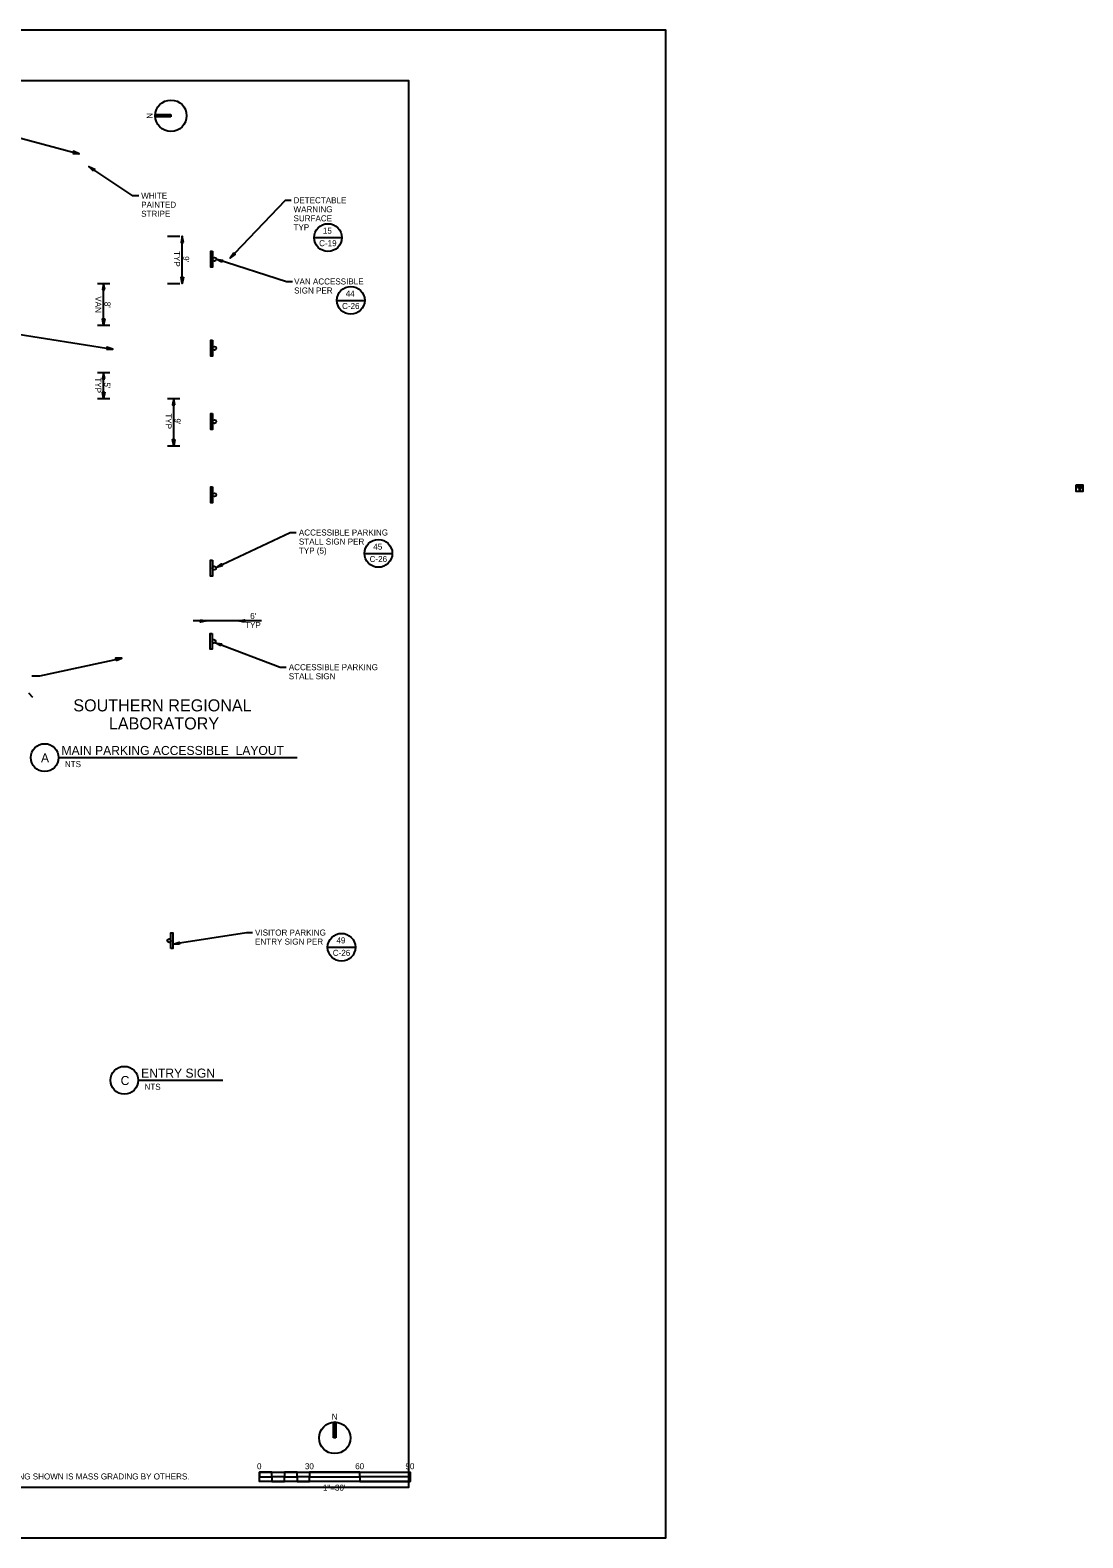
# Model space of a CAD drawing. Extents: x 0 to 4.19, y 0 to 2.5.
# Drawn here: x 2.446 to 4.191, y 0 to 2.5 of the extents above; entities that cross this region are included whole.
import ezdxf

# ---------------------------------------------------------------- set-up
doc = ezdxf.new("R2010")
doc.units = 0
for name, color, linetype in [('C-MARK', 7, 'Continuous'), ('C-PRKG-CONC', 7, 'Continuous'), ('C-TEXT', 7, 'Continuous'), ('C-TEXT-SUBT', 7, 'Continuous'), ('C-TEXT-TITL', 7, 'Continuous'), ('Default', 7, 'Continuous'), ('G-SYMB', 7, 'Continuous'), ('G-TEXT', 7, 'Continuous'), ('G-TTLB-OTLN', 7, 'Continuous'), ('G-TTLB-VIEW', 7, 'Continuous'), ('Level 11', 7, 'Continuous')]:
    doc.layers.add(name, color=color, linetype=linetype)

# ---------------------------------------------------------------- blocks, each defined once
blk = doc.blocks.new('G-handy2')
at = {"layer": 'Default'}
for p, q in [((-0.0006, 0.0019), (-0.0004, 0.0015)), ((0, 0), (-0.0002, 0.0036)), ((0, 0), (0.0033, 0)), ((0.0004, 0.0014), (0.0003, 0.0028)), ((0.0021, 0.0014), (0.0004, 0.0014)), ((0.0004, 0.0009), (0.0021, 0.0009)), ((0.0004, 0.0005), (0.0004, 0.0009)), ((0.0004, 0.0005), (0.0037, 0.0005)), ((0.0021, 0.0009), (0.0021, 0.0014)), ((0.0033, 0), (0.0039, -0.0023)), ((0.0037, 0.0005), (0.0042, -0.0017)), ((0.0027, -0.0011), (0.0031, -0.0012)), ((0.0039, -0.0023), (0.0049, -0.002)), ((0.0042, -0.0017), (0.0048, -0.0015)), ((0.0048, -0.0015), (0.0049, -0.002))]:
    blk.add_line(p, q, dxfattribs=at)
for centre, radius, start, end in [((0.0007, -0.0004), 0.00261, 117.724, 341.902), ((0.0007, -0.0004), 0.00219, 117.724, 341.902), ((0.0005, 0.0035), 0.000712, 254.4441, 174.7331)]:
    blk.add_arc(centre, radius, start, end, dxfattribs=at)

msp = doc.modelspace()

# ---------------------------------------------------------------- linework, layer by layer
at = {"layer": 'C-MARK'}
for p, q in [((2.6734, 2.1583), (2.6937, 2.1583)), ((2.6978, 2.0801), (2.6978, 2.1583)), ((2.9164, 2.1561), (2.9624, 2.1561)), ((2.5571, 2.0801), (2.5774, 2.0801)), ((2.5673, 2.0107), (2.5673, 2.0801)), ((2.6733, 2.0801), (2.6935, 2.0801)), ((2.9543, 2.0519), (3.0003, 2.0519)), ((2.5571, 2.0107), (2.5774, 2.0107)), ((2.5571, 1.9326), (2.5774, 1.9326)), ((2.5673, 1.8892), (2.5673, 1.9326)), ((2.5571, 1.8892), (2.5774, 1.8892)), ((2.6734, 1.8892), (2.6937, 1.8892)), ((2.6836, 1.811), (2.6836, 1.8892)), ((2.6733, 1.811), (2.6935, 1.811)), ((3.0001, 1.6323), (3.0461, 1.6323)), ((2.8291, 1.5204), (2.7156, 1.5204)), ((2.9389, 0.9793), (2.9849, 0.9793))]:
    msp.add_line(p, q, dxfattribs=at)
for points in [[(2.3741, 2.3331), (2.3841, 2.3331), (2.527, 2.2947)], [(2.626, 2.2252), (2.616, 2.2252), (2.5429, 2.2737)], [(2.8804, 2.0828), (2.8704, 2.0828), (2.7542, 2.1201)], [(2.4051, 1.9978), (2.4151, 1.9978), (2.5829, 1.9711)], [(2.8869, 1.6665), (2.8769, 1.6665), (2.7543, 1.6092)], [(2.8701, 1.4432), (2.8601, 1.4432), (2.7525, 1.4843)], [(2.4483, 1.4292), (2.4617, 1.4292), (2.5978, 1.4589)], [(2.8142, 1.0032), (2.8042, 1.0032), (2.6829, 0.9845)]]:
    msp.add_lwpolyline(points, dxfattribs=at)
for points in [[(2.7482, 2.1333), (2.7482, 2.1069), (2.745, 2.1069), (2.745, 2.1333)], [(2.7482, 1.9858), (2.7482, 1.9594), (2.745, 1.9594), (2.745, 1.9858)], [(2.7482, 1.8642), (2.7482, 1.8378), (2.745, 1.8378), (2.745, 1.8642)], [(2.7482, 1.7427), (2.7482, 1.7163), (2.745, 1.7163), (2.745, 1.7427)], [(2.7478, 1.6212), (2.7478, 1.5948), (2.7446, 1.5948), (2.7446, 1.6212)], [(2.7474, 1.4997), (2.7474, 1.4733), (2.7442, 1.4733), (2.7442, 1.4997)], [(2.6789, 0.977), (2.6789, 1.0034), (2.6821, 1.0034), (2.6821, 0.977)]]:
    msp.add_lwpolyline(points, close=True, dxfattribs=at)
for centre, radius in [((2.9394, 2.1561), 0.023), ((2.7512, 2.1201), 0.003), ((2.9773, 2.0519), 0.023), ((2.7512, 1.9726), 0.003), ((2.7512, 1.851), 0.003), ((2.7512, 1.7295), 0.003), ((3.0231, 1.6323), 0.023), ((2.7508, 1.608), 0.003), ((2.7504, 1.4865), 0.003), ((2.9619, 0.9793), 0.023), ((2.6759, 0.9902), 0.003)]:
    msp.add_circle(centre, radius, dxfattribs=at)
at = {"layer": 'C-PRKG-CONC'}
msp.add_lwpolyline([(4.1803, 1.7463), (4.1914, 1.7463), (4.1914, 1.7352), (4.1803, 1.7352)], close=True, dxfattribs=at)
msp.add_lwpolyline([(4.1803, 1.7463), (4.1914, 1.7463), (4.1914, 1.7352), (4.1803, 1.7352)], close=True, dxfattribs=at)
at = {"layer": 'C-TEXT'}
for p, q in [((2.4926, 1.2938), (2.8882, 1.2938)), ((2.6247, 0.7588), (2.7651, 0.7588))]:
    msp.add_line(p, q, dxfattribs=at)
for points in [[(2.5165, 2.2956), (2.527, 2.2947), (2.5174, 2.2992)], [(2.5505, 2.2664), (2.5429, 2.2737), (2.5526, 2.2695)], [(2.6996, 2.1478), (2.6978, 2.1583), (2.6959, 2.1478)], [(2.7832, 2.1307), (2.7773, 2.1219), (2.7858, 2.1282)], [(2.7636, 2.1152), (2.7542, 2.1201), (2.7647, 2.1187)], [(2.5691, 2.0697), (2.5673, 2.0801), (2.5655, 2.0697)], [(2.6996, 2.0905), (2.6978, 2.0801), (2.6959, 2.0905)], [(2.5691, 2.0211), (2.5673, 2.0107), (2.5655, 2.0211)], [(2.5723, 1.9709), (2.5829, 1.9711), (2.5729, 1.9745)], [(2.5691, 1.9221), (2.5673, 1.9326), (2.5655, 1.9221)], [(2.5691, 1.8996), (2.5673, 1.8892), (2.5655, 1.8996)], [(2.6854, 1.8787), (2.6836, 1.8892), (2.6817, 1.8787)], [(2.6854, 1.8215), (2.6836, 1.811), (2.6817, 1.8215)], [(2.7645, 1.6119), (2.7543, 1.6092), (2.7629, 1.6152)], [(2.7281, 1.5222), (2.7385, 1.5204), (2.7281, 1.5185)], [(2.8008, 1.5185), (2.7904, 1.5204), (2.8008, 1.5222)], [(2.7616, 1.4789), (2.7525, 1.4843), (2.7629, 1.4823)], [(2.588, 1.4549), (2.5978, 1.4589), (2.5873, 1.4584)], [(2.6934, 0.9843), (2.6829, 0.9845), (2.6929, 0.9879)]]:
    msp.add_lwpolyline(points, close=True, dxfattribs=at)
msp.add_lwpolyline([(2.8786, 2.2175), (2.8686, 2.2175), (2.7845, 2.1294)], dxfattribs=at)
for centre in [(2.4696, 1.2938), (2.6017, 0.7588)]:
    msp.add_circle(centre, 0.023, dxfattribs=at)
at = {"layer": 'G-SYMB'}
for p, q in [((2.679, 2.3586), (2.6532, 2.3586)), ((2.679, 2.3577), (2.6532, 2.3577)), ((2.6533, 2.36), (2.679, 2.36)), ((2.679, 2.3563), (2.6533, 2.3563)), ((2.679, 2.36), (2.679, 2.3563)), ((2.9488, 0.1657), (2.9488, 0.1915)), ((2.9503, 0.1657), (2.9503, 0.1915)), ((2.9511, 0.1657), (2.9511, 0.1915)), ((2.9525, 0.1915), (2.9525, 0.1657)), ((2.9525, 0.1657), (2.9488, 0.1657))]:
    msp.add_line(p, q, dxfattribs=at)
for points in [[(2.8257, 0.101), (2.8465, 0.101), (2.8465, 0.1088), (2.8257, 0.1088)], [(2.8257, 0.1088), (3.0757, 0.1088), (3.0757, 0.0932), (2.8257, 0.0932)], [(2.8465, 0.0932), (2.8673, 0.0932), (2.8673, 0.101), (2.8465, 0.101)], [(2.8673, 0.101), (2.8882, 0.101), (2.8882, 0.1088), (2.8673, 0.1088)], [(2.8882, 0.0932), (2.909, 0.0932), (2.909, 0.101), (2.8882, 0.101)], [(2.909, 0.101), (2.9923, 0.101), (2.9923, 0.1088), (2.909, 0.1088)], [(2.9923, 0.0932), (3.0757, 0.0932), (3.0757, 0.101), (2.9923, 0.101)]]:
    msp.add_lwpolyline(points, close=True, dxfattribs=at)
for centre in [(2.679, 2.3581), (2.9507, 0.1657)]:
    msp.add_circle(centre, 0.026, dxfattribs=at)
for centre, start, end in [((2.678, 2.3581), 175.7578, 184.2422), ((2.9507, 0.1668), 85.7578, 94.2422)]:
    msp.add_arc(centre, 0.0248, start, end, dxfattribs=at)
at = {"layer": 'G-TTLB-OTLN'}
msp.add_lwpolyline([(0, 0), (3.5, 0), (3.5, 2.5), (0, 2.5)], close=True, dxfattribs=at)
msp.add_lwpolyline([(0, 0), (3.5, 0), (3.5, 2.5), (0, 2.5)], close=True, dxfattribs=at)
at = {"layer": 'G-TTLB-VIEW'}
msp.add_lwpolyline([(0.1667, 2.4167), (3.0729, 2.4167), (3.0729, 0.0833), (0.1667, 0.0833)], close=True, dxfattribs=at)
at = {"layer": 'Level 11'}
msp.add_line((2.4502, 1.3937), (2.4433, 1.4005), dxfattribs=at)

# ---------------------------------------------------------------- block references
at = {"layer": 'C-PRKG-CONC', "xscale": 1.1453414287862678, "yscale": 1.1453414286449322, "rotation": 179.73949444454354}
msp.add_blockref('G-handy2', (4.1867, 1.7415), dxfattribs=at)

# ---------------------------------------------------------------- texts
at = {"layer": 'C-TEXT'}
for s, p in [('WHITE', (2.6297, 2.2205)), ('STRIPE', (2.6297, 2.1905)), ('PAINTED', (2.6297, 2.2055)), ('WARNING', (2.8823, 2.198)), ('DETECTABLE', (2.8823, 2.213)), ('TYP', (2.8823, 2.168)), ('SURFACE', (2.8823, 2.183)), ('C-19', (2.9248, 2.1418)), ('15', (2.931, 2.1625)), ('VAN ACCESSIBLE', (2.8833, 2.0783)), ('SIGN PER', (2.8833, 2.0633)), ('44', (2.9689, 2.0582)), ('C-26', (2.9628, 2.0376)), ('ACCESSIBLE PARKING', (2.8912, 1.662)), ('STALL SIGN PER', (2.8912, 1.647)), ('TYP (5)', (2.8912, 1.632)), ('C-26', (3.0085, 1.618)), ('45', (3.0146, 1.6386)), ("6'", (2.8104, 1.5235)), ('TYP', (2.802, 1.5085)), ('ACCESSIBLE PARKING', (2.8745, 1.4387)), ('STALL SIGN', (2.8745, 1.4237)), ('NTS', (2.5031, 1.278)), ('VISITOR PARKING', (2.8185, 0.9987)), ('ENTRY SIGN PER', (2.8185, 0.9837)), ('C-26', (2.9474, 0.965)), ('49', (2.9535, 0.9857)), ('NTS', (2.6352, 0.7429)), ('GRADING SHOWN IS MASS GRADING BY OTHERS.', (2.3837, 0.0968))]:
    msp.add_text(s, height=0.01, dxfattribs=at).set_placement(p)
for s, p in [('TYP', (2.6842, 2.1337)), ("9'", (2.6992, 2.1253)), ('VAN', (2.5538, 2.0587)), ("8'", (2.5688, 2.0496)), ('TYP', (2.5533, 1.9243)), ("5'", (2.5683, 1.9159)), ('TYP', (2.67, 1.8646)), ("9'", (2.685, 1.8562))]:
    msp.add_text(s, height=0.01, rotation=270, dxfattribs=at).set_placement(p)
at = {"layer": 'C-TEXT-SUBT'}
for s, p in [('A', (2.4635, 1.2859)), ('MAIN PARKING ACCESSIBLE  LAYOUT', (2.4975, 1.2981)), ('ENTRY SIGN', (2.6296, 0.7631)), ('C', (2.5956, 0.7508))]:
    msp.add_text(s, height=0.015, dxfattribs=at).set_placement(p)
at = {"layer": 'C-TEXT-TITL'}
for s, p in [('SOUTHERN REGIONAL', (2.5171, 1.3704)), ('LABORATORY', (2.5761, 1.3404))]:
    msp.add_text(s, height=0.02, dxfattribs=at).set_placement(p)
at = {"layer": 'G-SYMB'}
msp.add_text('N', height=0.01, rotation=90, dxfattribs=at).set_placement((2.6487, 2.3531))
msp.add_text('N', height=0.01, dxfattribs=at).set_placement((2.9456, 0.196))
at = {"layer": 'G-TEXT'}
for s, p in [('0', (2.8218, 0.1138)), ('30', (2.9012, 0.1138)), ('60', (2.9846, 0.1138)), ('90', (3.0679, 0.1138)), ('1"=30\'', (2.9311, 0.0782))]:
    msp.add_text(s, height=0.01, dxfattribs=at).set_placement(p)

doc.saveas('drawing.dxf')
